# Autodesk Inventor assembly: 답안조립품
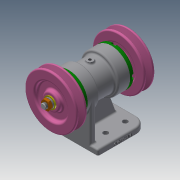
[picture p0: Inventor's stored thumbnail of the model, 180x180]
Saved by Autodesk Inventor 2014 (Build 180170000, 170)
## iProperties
Created: 2020-06
Part Number: 답안조립품
Document SubType Name: Assembly
Designer: kh
Author: kh
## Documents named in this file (13)
- C:\Users\kh\Desktop\700606V1032\답안조립품.iam
- C:\Users\kh\Desktop\700606V1032\본체.ipt
- C:\Users\kh\Desktop\700606V1032\축.ipt
- C:\Users\kh\Desktop\700606V1032\Ű 5x5x12.ipt
- C:\Users\kh\Desktop\700606V1032\커버.ipt
- C:\Users\kh\Desktop\700606V1032\볼트 M4.ipt
- C:\Users\kh\Desktop\700606V1032\오일 실 20 32 5.ipt
- C:\Users\kh\Desktop\700606V1032\베어링 6204.ipt
- C:\Users\kh\Desktop\700606V1032\커버_MIR.ipt
- C:\Users\kh\Desktop\700606V1032\V-벨트풀리.ipt
- C:\Users\kh\Desktop\700606V1032\너트 M10.ipt
- C:\Users\kh\Desktop\700606V1032\스프링 와셔 10.ipt
- C:\Users\kh\Desktop\700606V1032\평면 와셔 10x21.ipt
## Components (4 placed, 2 different names)
1. Ű 5x5x12:1 — Mate:1, Mate:5, Mate:6, Mate:37, Angle:1
2. Ű 5x5x12:2 — Mate:2, Mate:3, Mate:4, Mate:22
3. V-벨트풀리:1 — Mate:21, Mate:22, Mate:28, Mate:29
4. V-벨트풀리:2 — Mate:33, Mate:37, Mate:38
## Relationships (14: Mate 13, Angle 1)
- Mate:1: Ű 5x5x12:1
- Mate:2: Ű 5x5x12:2
- Mate:3: Ű 5x5x12:2
- Mate:4: Ű 5x5x12:2
- Mate:5: Ű 5x5x12:1
- Mate:6: Ű 5x5x12:1
- Mate:21: V-벨트풀리:1
- Mate:22: Ű 5x5x12:2 ↔ V-벨트풀리:1
- Mate:28: V-벨트풀리:1
- Mate:29: V-벨트풀리:1
- Mate:33: V-벨트풀리:2
- Mate:37: Ű 5x5x12:1 ↔ V-벨트풀리:2
- Mate:38: V-벨트풀리:2
- Angle:1: Ű 5x5x12:1
## Named parameters: d35_d33 = 0, d36_d31 = 0, d37_d32 = 0
